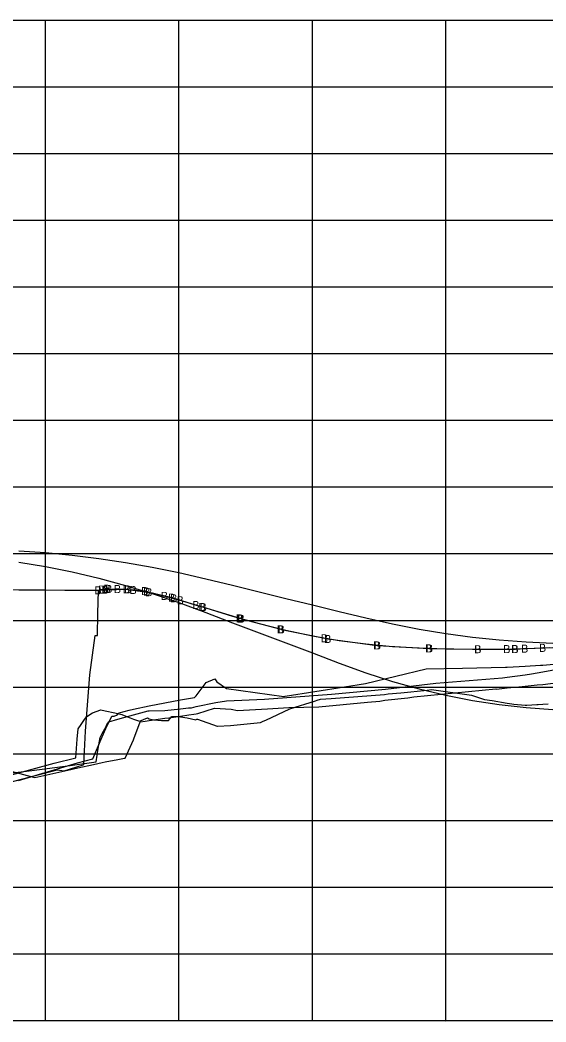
# Model space of a CAD drawing. Extents: x 76292 to 78417, y 50412 to 52585.
# Drawn here: x 76695.8 to 76892.8, y 50411.8 to 50787.3 of the extents above; entities that cross this region are included whole.
import ezdxf

# ---------------------------------------------------------------- set-up
doc = ezdxf.new("R2010")
doc.units = 0
for name, color, linetype in [('1', 7, 'Continuous'), ('2', 7, 'Continuous'), ('38', 7, 'Continuous'), ('5', 7, 'Continuous'), ('63', 7, 'Continuous')]:
    doc.layers.add(name, color=color, linetype=linetype)

msp = doc.modelspace()

# ---------------------------------------------------------------- linework, layer by layer
at = {"layer": '1'}
for p, q in [((76305.34, 50412.34), (78205.34, 50412.34)), ((76705.34, 50412.34), (76705.34, 50412.34)), ((76755.34, 50412.34), (76755.34, 50412.34)), ((76805.34, 50412.34), (76805.34, 50412.34)), ((76855.34, 50412.34), (76855.34, 50412.34))]:
    msp.add_line(p, q, dxfattribs=at)
for points in [[(76683.8, 50504.01), (76700.19, 50506.03), (76714.52, 50507.98), (76724.27, 50509.34), (76725.07, 50514.27), (76725.79, 50518.4), (76726.58, 50519.91), (76727.53, 50521.71), (76728.13, 50522.88), (76728.31, 50523.25), (76729.1, 50524.32), (76732.46, 50525.31), (76738.33, 50526.95), (76743.8, 50528.37), (76744.2, 50528.39), (76750.04, 50528.51), (76750.08, 50528.55), (76755.95, 50529.19), (76758.91, 50529.49), (76759.97, 50529.61), (76761.83, 50530.06), (76769.16, 50531.55), (76773.11, 50532.17), (76787.33, 50532.77), (76812.42, 50534.7), (76832.67, 50536.59), (76851.57, 50538.74), (76876.53, 50540.77), (76878.33, 50541), (76885.01, 50541.93), (76887.46, 50542.25), (76891.7, 50543.03), (76898.38, 50544.24)], [(76695.17, 50502.34), (76717.36, 50508.88), (76723.01, 50510.41), (76726.58, 50518.71), (76727.89, 50521.75), (76730.13, 50526.37), (76731.11, 50526.47), (76731.92, 50526.76), (76732.46, 50527.18), (76732.89, 50527.69), (76736.63, 50528.69), (76738.33, 50529.03), (76744.2, 50530.25), (76750.08, 50531.4), (76755.95, 50532.51), (76761.15, 50533.46), (76761.83, 50534.11), (76765.58, 50539.02), (76768.72, 50540.4), (76769.46, 50539.3), (76773.11, 50536.86), (76794.62, 50533.83), (76794.71, 50533.85), (76794.76, 50533.85), (76795.1, 50533.88), (76817.31, 50537.42), (76825.21, 50538.62), (76847.88, 50544.11), (76861.52, 50544.36), (76877.71, 50544.8), (76878.33, 50544.84), (76885.01, 50545.21), (76890.76, 50545.52), (76891.7, 50545.59), (76898.38, 50546.18)], [(76690.6, 50506.27), (76700.36, 50503.69), (76701.33, 50503.42), (76713.7, 50506.22), (76717.38, 50507.04), (76723.25, 50508.31), (76726.58, 50509.02), (76727.67, 50509.25), (76732.46, 50510.17), (76734.87, 50510.66), (76734.96, 50510.68), (76735.19, 50510.73), (76738.33, 50517.56), (76738.47, 50517.91), (76740.74, 50524.28), (76742.72, 50524.6), (76744.2, 50524.77), (76750.08, 50525.63), (76751.59, 50525.86), (76755.95, 50526.47), (76759.05, 50526.93), (76760.84, 50527.22), (76761.83, 50527.33), (76762.43, 50527.44), (76768.63, 50529.45), (76774.91, 50529.11), (76777.27, 50528.57), (76788.5, 50529.15), (76796.54, 50529.69), (76807.7, 50529.93), (76825.97, 50531.63), (76830.54, 50532.08), (76832.49, 50532.44), (76841.03, 50533.34), (76843.31, 50533.7), (76874, 50536.65), (76874.3, 50536.59), (76878.33, 50537), (76881.02, 50537.27), (76882.61, 50537.44), (76885.01, 50537.65), (76889.56, 50538.13), (76891.7, 50538.36), (76898.38, 50539.18)], [(76688.47, 50503.33), (76708.61, 50508.87), (76716.73, 50510.8), (76717.2, 50517.84), (76717.55, 50521.67), (76718.73, 50523.34), (76719.97, 50525.17), (76720.75, 50526.32), (76722.96, 50527.74), (76726.08, 50528.82), (76726.58, 50528.71), (76732.46, 50527.42), (76733.93, 50527.11), (76735.41, 50526.44), (76737.07, 50525.77), (76738.33, 50525.25), (76738.69, 50525.13), (76740.57, 50524.6), (76743.58, 50525.8), (76744.2, 50525.49), (76744.66, 50525.32), (76745.98, 50525.02), (76748.73, 50524.78), (76750.08, 50524.79), (76751.46, 50524.81), (76752.61, 50526.36), (76755.81, 50526.25), (76755.95, 50526.2), (76758.43, 50525.83), (76761.68, 50525.06), (76761.83, 50525.21), (76761.98, 50525.28), (76762.23, 50525.27), (76769.62, 50522.64), (76769.73, 50522.64), (76769.81, 50522.65), (76774.68, 50522.95), (76778.38, 50523.3), (76785.89, 50524.08), (76786.83, 50524.57), (76787.85, 50524.98), (76796.88, 50529.23), (76806.45, 50532.2), (76807.1, 50532.45), (76808.36, 50532.74), (76812.29, 50533.01), (76817.37, 50533.37), (76822.36, 50533.75), (76827.31, 50534.16), (76832.29, 50534.61), (76833.68, 50534.75), (76838.5, 50535.21), (76848.31, 50536.23), (76849.88, 50536.4), (76864.86, 50534.3), (76869.75, 50532.64), (76872.63, 50532.31), (76878.33, 50531.36), (76880.09, 50531.04), (76880.84, 50530.93), (76885.01, 50530.6), (76885.59, 50530.53), (76889.37, 50530.82), (76889.85, 50530.83), (76891.7, 50530.96), (76893.67, 50531.08)]]:
    msp.add_lwpolyline(points, dxfattribs=at)
at = {"layer": '2'}
msp.add_lwpolyline([(76688.77, 50500.8), (76709.75, 50506.34), (76712.3, 50505.93), (76719.48, 50508.17), (76719.63, 50508.36), (76720.3, 50520.86), (76721.89, 50541.93), (76723.92, 50556.67), (76724.25, 50556.64), (76724.76, 50556.62), (76724.97, 50564.95), (76725.17, 50573.59), (76726.49, 50573.88), (76726.58, 50573.88), (76727.83, 50573.83), (76728.54, 50574.19), (76728.58, 50574.17), (76729.16, 50574.12), (76732.46, 50574.07), (76735.74, 50574.02), (76736.3, 50573.93), (76738.33, 50573.73), (76742.7, 50573.32), (76743.46, 50573.08), (76744.2, 50572.9), (76750.08, 50571.51), (76752.74, 50570.89), (76753.52, 50570.62), (76755.95, 50569.87), (76761.83, 50568.09), (76764.15, 50567.39), (76764.57, 50567.26), (76778.17, 50563.1), (76778.48, 50563.01), (76778.78, 50562.94), (76793.43, 50558.99), (76793.6, 50558.96), (76793.79, 50558.93), (76810.01, 50555.62), (76811.2, 50555.37), (76811.21, 50555.37), (76811.22, 50555.36), (76829.53, 50552.95), (76829.69, 50552.93), (76829.86, 50552.92), (76848.99, 50551.81), (76849.16, 50551.81), (76849.33, 50551.81), (76867.38, 50551.52), (76867.49, 50551.53), (76878.33, 50551.56), (76881.27, 50551.57), (76881.39, 50551.58), (76885.01, 50551.73), (76891.7, 50552.01), (76894.14, 50552.12)], dxfattribs=at)
at = {"layer": '38'}
for points in [[(76695.34, 50588.45), (76705.34, 50587.75), (76715.34, 50586.79), (76725.34, 50585.55), (76735.34, 50584.05), (76745.34, 50582.27), (76755.34, 50580.23), (76765.34, 50577.92), (76775.34, 50575.47), (76785.34, 50573.03), (76795.34, 50570.58), (76805.34, 50568.13), (76815.34, 50565.68), (76825.34, 50563.24), (76835.34, 50560.99), (76845.34, 50559.04), (76855.34, 50557.39), (76865.34, 50556.05), (76875.34, 50555.01), (76885.34, 50554.27), (76895.34, 50553.83)], [(76695.34, 50584.18), (76705.34, 50582.53), (76715.34, 50580.53), (76725.34, 50578.17), (76735.34, 50575.46), (76745.34, 50572.39), (76755.34, 50568.97), (76765.34, 50565.23), (76775.34, 50561.46), (76785.34, 50557.68), (76795.34, 50553.9), (76805.34, 50550.12), (76815.34, 50546.34), (76825.34, 50542.69), (76835.34, 50539.44), (76845.34, 50536.63), (76855.34, 50534.24), (76865.34, 50532.28), (76875.34, 50530.74), (76885.34, 50529.64), (76895.34, 50528.96)], [(76695.34, 50573.81), (76705.34, 50573.73), (76715.34, 50573.66), (76725.34, 50573.63), (76735.34, 50574.03), (76745.34, 50572.63), (76755.34, 50570.06), (76765.34, 50567.02), (76775.34, 50563.96), (76785.34, 50561.17), (76795.34, 50558.61), (76805.34, 50556.57), (76815.34, 50554.82), (76825.34, 50553.5), (76835.34, 50552.6), (76845.34, 50552.02), (76855.34, 50551.71), (76865.34, 50551.56), (76875.34, 50551.55), (76885.34, 50551.75), (76895.34, 50552.16)], [(76695.34, 50573.81), (76705.34, 50573.73), (76715.34, 50573.66), (76725.34, 50573.63), (76735.34, 50574.03), (76745.34, 50572.63), (76755.34, 50570.06), (76765.34, 50567.02), (76775.34, 50563.96), (76785.34, 50561.17), (76795.34, 50558.61), (76805.34, 50556.57), (76815.34, 50554.82), (76825.34, 50553.5), (76835.34, 50552.6), (76845.34, 50552.02), (76855.34, 50551.71), (76865.34, 50551.56), (76875.34, 50551.55), (76885.34, 50551.75), (76895.34, 50552.16)]]:
    msp.add_lwpolyline(points, dxfattribs=at)
at = {"layer": '5'}
for p, q in [((76647.72, 50574.16), (76725.17, 50573.59)), ((76725.17, 50573.59), (76726.49, 50573.88)), ((76726.49, 50573.88), (76726.58, 50573.88)), ((76726.58, 50573.88), (76727.83, 50573.83)), ((76727.83, 50573.83), (76728.54, 50574.19)), ((76728.54, 50574.19), (76728.58, 50574.17)), ((76728.58, 50574.17), (76729.16, 50574.12)), ((76729.16, 50574.12), (76732.46, 50574.07)), ((76732.46, 50574.07), (76735.74, 50574.02)), ((76735.74, 50574.02), (76736.3, 50573.93)), ((76736.3, 50573.93), (76738.33, 50573.73)), ((76738.33, 50573.73), (76742.7, 50573.32)), ((76742.7, 50573.32), (76743.46, 50573.08)), ((76743.46, 50573.08), (76744.2, 50572.9)), ((76744.2, 50572.9), (76750.08, 50571.51)), ((76750.08, 50571.51), (76752.74, 50570.89)), ((76752.74, 50570.89), (76753.52, 50570.62)), ((76753.52, 50570.62), (76755.95, 50569.87)), ((76755.95, 50569.87), (76761.83, 50568.09)), ((76761.83, 50568.09), (76764.15, 50567.39)), ((76764.15, 50567.39), (76764.57, 50567.26)), ((76764.57, 50567.26), (76778.17, 50563.1)), ((76778.17, 50563.1), (76778.48, 50563.01)), ((76778.48, 50563.01), (76778.78, 50562.94)), ((76778.78, 50562.94), (76793.43, 50558.99)), ((76793.43, 50558.99), (76793.6, 50558.96)), ((76793.6, 50558.96), (76793.79, 50558.93)), ((76793.79, 50558.93), (76810.01, 50555.62)), ((76810.01, 50555.62), (76811.2, 50555.37)), ((76811.2, 50555.37), (76811.21, 50555.37)), ((76811.21, 50555.37), (76811.22, 50555.36)), ((76811.22, 50555.36), (76829.53, 50552.95)), ((76829.53, 50552.95), (76829.69, 50552.93)), ((76829.69, 50552.93), (76829.86, 50552.92)), ((76829.86, 50552.92), (76848.99, 50551.81)), ((76848.99, 50551.81), (76849.16, 50551.81)), ((76849.16, 50551.81), (76849.33, 50551.81)), ((76849.33, 50551.81), (76867.38, 50551.52)), ((76867.38, 50551.52), (76867.49, 50551.53)), ((76867.49, 50551.53), (76878.33, 50551.56)), ((76878.33, 50551.56), (76881.27, 50551.57)), ((76881.27, 50551.57), (76881.39, 50551.58)), ((76881.39, 50551.58), (76885.01, 50551.73)), ((76885.01, 50551.73), (76891.7, 50552.01)), ((76891.7, 50552.01), (76894.14, 50552.12))]:
    msp.add_line(p, q, dxfattribs=at)
at = {"layer": '63'}
for p, q in [((76305.34, 50787.34), (78205.34, 50787.34)), ((76305.34, 50787.34), (78205.34, 50787.34)), ((76705.34, 50412.34), (76705.34, 50787.34)), ((76755.34, 50412.34), (76755.34, 50787.34)), ((76805.34, 50412.34), (76805.34, 50787.34)), ((76855.34, 50412.34), (76855.34, 50787.34)), ((76305.34, 50762.34), (78205.34, 50762.34)), ((76305.34, 50737.34), (78205.34, 50737.34)), ((76305.34, 50712.34), (78205.34, 50712.34)), ((76305.34, 50687.34), (78205.34, 50687.34)), ((76305.34, 50662.34), (78205.34, 50662.34)), ((76305.34, 50637.34), (78205.34, 50637.34)), ((76305.34, 50612.34), (78205.34, 50612.34)), ((76305.34, 50587.34), (78205.34, 50587.34)), ((76305.34, 50562.34), (78205.34, 50562.34)), ((76305.34, 50537.34), (78205.34, 50537.34)), ((76305.34, 50512.34), (78205.34, 50512.34)), ((76305.34, 50487.34), (78205.34, 50487.34)), ((76305.34, 50462.34), (78205.34, 50462.34)), ((76305.34, 50437.34), (78205.34, 50437.34))]:
    msp.add_line(p, q, dxfattribs=at)

# ---------------------------------------------------------------- texts
at = {"layer": '1'}
for s, p in [('84', (76705.4, 50411.94)), ('+50', (76755.4, 50411.81)), ('85', (76805.4, 50411.94)), ('+50', (76855.4, 50411.81))]:
    msp.add_text(s, height=0.12, rotation=90, dxfattribs=at).set_placement(p)
at = {"layer": '5'}
for p in [(76723.67, 50572.09), (76724.99, 50572.38), (76725.08, 50572.38), (76726.33, 50572.33), (76727.04, 50572.69), (76727.08, 50572.67), (76727.66, 50572.62), (76730.96, 50572.57), (76734.24, 50572.52), (76734.8, 50572.43), (76736.83, 50572.23), (76741.2, 50571.82), (76741.96, 50571.58), (76742.7, 50571.4), (76748.58, 50570.01), (76751.24, 50569.39), (76752.02, 50569.12), (76754.45, 50568.37), (76760.33, 50566.59), (76762.65, 50565.89), (76763.07, 50565.76), (76776.67, 50561.6), (76776.98, 50561.51), (76777.28, 50561.44), (76791.93, 50557.49), (76792.1, 50557.46), (76792.29, 50557.43), (76808.51, 50554.12), (76809.7, 50553.87), (76809.71, 50553.87), (76809.72, 50553.86), (76828.03, 50551.45), (76828.19, 50551.43), (76828.36, 50551.42), (76847.49, 50550.31), (76847.66, 50550.31), (76847.83, 50550.31), (76865.88, 50550.02), (76865.99, 50550.03), (76876.83, 50550.06), (76879.77, 50550.07), (76879.89, 50550.08), (76883.51, 50550.23), (76890.2, 50550.51)]:
    msp.add_text('B', height=3, dxfattribs=at).set_placement(p)

doc.saveas('drawing.dxf')
